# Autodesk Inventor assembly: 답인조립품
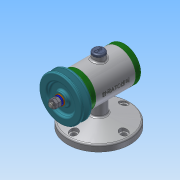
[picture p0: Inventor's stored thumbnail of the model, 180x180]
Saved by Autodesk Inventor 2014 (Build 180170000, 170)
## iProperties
Created: 2018-12
Part Number: 답인조립품
Document SubType Name: Assembly
Designer: sda
Author: sda
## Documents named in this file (15)
- C:\Users\sda\Desktop\481207V1061\답인조립품.iam
- C:\Users\sda\Desktop\481207V1061\V벨트풀리.ipt
- C:\Users\sda\Desktop\481207V1061\고무캡.ipt
- C:\Users\sda\Desktop\481207V1061\너트 M8.ipt
- 너트 M8.ipt
- C:\Users\sda\Desktop\481207V1061\뒤커버.ipt
- C:\Users\sda\Desktop\481207V1061\베어링 15 x 32 x 9.ipt
- C:\Users\sda\Desktop\481207V1061\본체.ipt
- C:\Users\sda\Desktop\481207V1061\볼트 M4 x 12.ipt
- C:\Users\sda\Desktop\481207V1061\스프링와셔 8.ipt
- C:\Users\sda\Desktop\481207V1061\앞커버.ipt
- C:\Users\sda\Desktop\481207V1061\오일 실 15 25 7.ipt
- C:\Users\sda\Desktop\481207V1061\와셔 8x17.ipt
- C:\Users\sda\Desktop\481207V1061\축.ipt
- C:\Users\sda\Desktop\481207V1061\키 3 x 3 x 12.ipt
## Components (2 placed, 2 different names)
1. V벨트풀리:1
2. 고무캡:1 — 각도:4
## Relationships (1: Angle 1)
- 각도:4 [Angle]: 고무캡:1
